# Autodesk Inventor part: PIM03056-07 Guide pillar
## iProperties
Created: 2007-09
Part Number: PIM03056-07 Guide pillar
Description: Rd.
Document SubType Name: Modellieren
Designer: WH
Mass: 20551.7 g
Surface Area: 1448.92 cm^2
Volume: 2618.05 cm^3
Density: 7.85 g/cm^3
Material: 1.1221
Title: PIM03056-07 Guide pillar
Author: WH
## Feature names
1. Umdrehung2 [Revolution]
2. Bohrung1 [Hole]
